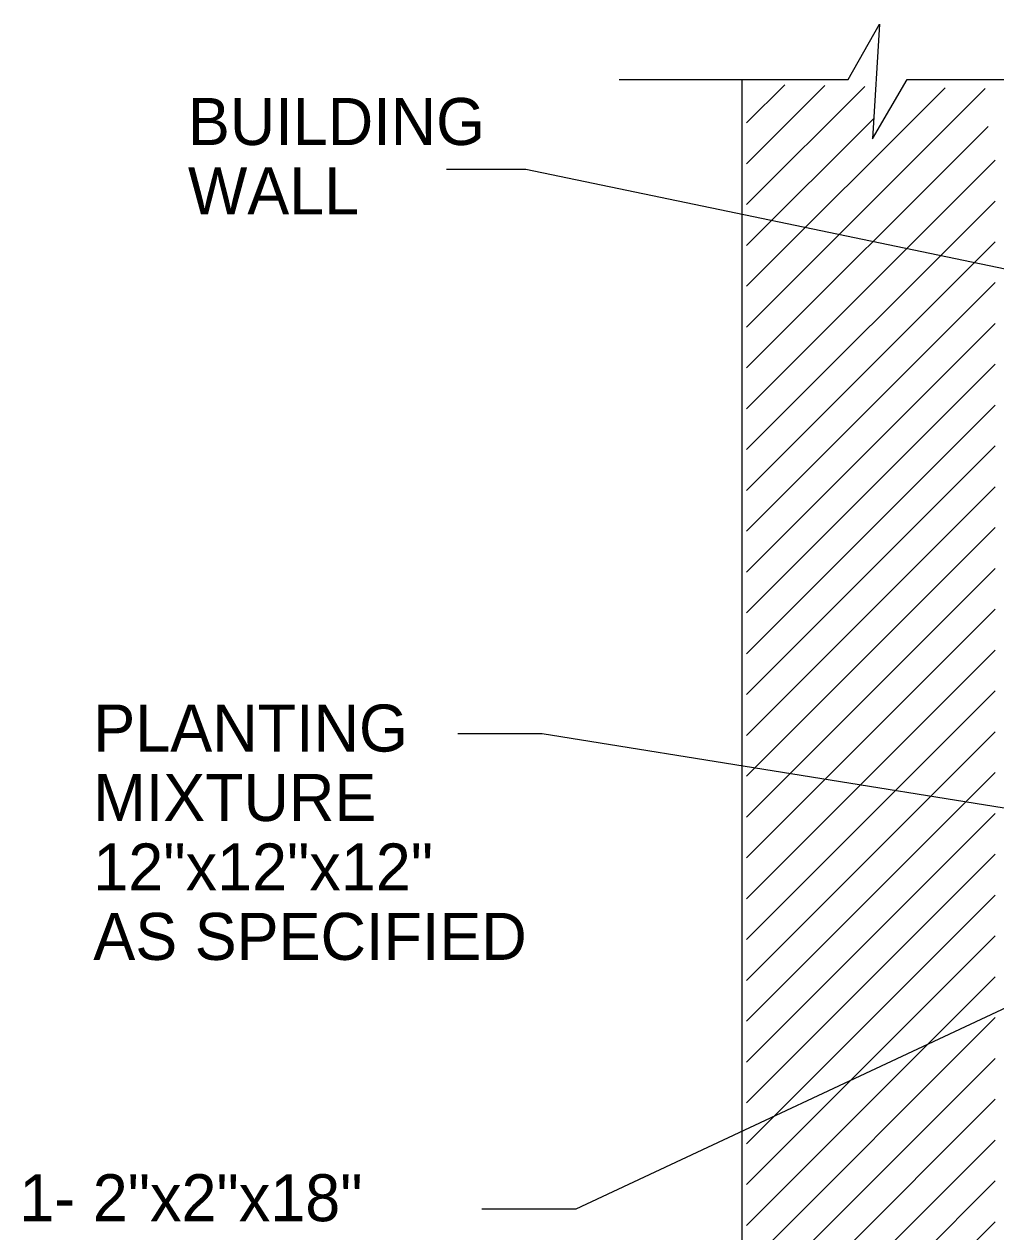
# Model space of a CAD drawing. Extents: x 10082 to 10257, y 10014 to 10069.
# Drawn here: x 10115.77 to 10130.23, y 10027 to 10044.97 of the extents above; entities that cross this region are included whole.
import ezdxf

# ---------------------------------------------------------------- set-up
doc = ezdxf.new("R2010")
doc.units = 0
for name, color, linetype in [('Default', 7, 'Continuous'), ('G-DETL-LINE', 7, 'Continuous'), ('G-DETL-PATT', 7, 'Continuous'), ('G-DETL-TEXT', 7, 'Continuous')]:
    doc.layers.add(name, color=color, linetype=linetype)

msp = doc.modelspace()

# ---------------------------------------------------------------- linework, layer by layer
at = {"layer": 'Default'}
for p, q in [((10123.231, 10042.808), (10122.053, 10042.808)), ((10132.364, 10040.908), (10123.231, 10042.808)), ((10123.475, 10034.406), (10122.219, 10034.406)), ((10134.29, 10032.667), (10123.475, 10034.406)), ((10136.446, 10033.178), (10123.976, 10027.333)), ((10123.976, 10027.333), (10122.578, 10027.333))]:
    msp.add_line(p, q, dxfattribs=at)
at = {"layer": 'G-DETL-LINE'}
for p, q in [((10128.03, 10044.143), (10128.493, 10044.969)), ((10128.493, 10044.969), (10128.39, 10043.262)), ((10124.618, 10044.143), (10128.03, 10044.143)), ((10128.39, 10043.262), (10128.904, 10044.143)), ((10128.904, 10044.143), (10132.704, 10044.143))]:
    msp.add_line(p, q, dxfattribs=at)
msp.add_lwpolyline([(10126.447, 10044.143), (10126.447, 10021.81)], dxfattribs=at)
at = {"layer": 'G-DETL-PATT'}
for p, q in [((10126.517, 10043.498), (10127.085, 10044.065)), ((10126.517, 10042.89), (10127.681, 10044.054)), ((10126.517, 10042.283), (10128.277, 10044.043)), ((10126.517, 10041.068), (10129.47, 10044.02)), ((10126.517, 10040.46), (10130.066, 10044.009)), ((10126.517, 10041.675), (10128.408, 10043.566)), ((10126.517, 10039.853), (10130.112, 10043.447)), ((10126.517, 10039.245), (10130.217, 10042.945)), ((10126.517, 10038.637), (10130.217, 10042.337)), ((10126.517, 10038.03), (10130.217, 10041.73)), ((10126.517, 10037.422), (10130.217, 10041.122)), ((10126.517, 10036.815), (10130.217, 10040.515)), ((10126.517, 10036.207), (10130.217, 10039.907)), ((10126.517, 10035.6), (10130.217, 10039.3)), ((10126.517, 10034.992), (10130.217, 10038.692)), ((10126.517, 10034.385), (10130.217, 10038.084)), ((10126.517, 10033.777), (10130.217, 10037.477)), ((10126.517, 10033.17), (10130.217, 10036.869)), ((10126.517, 10032.562), (10130.217, 10036.262)), ((10126.517, 10031.954), (10130.217, 10035.654)), ((10126.517, 10031.347), (10130.217, 10035.047)), ((10126.517, 10030.739), (10130.217, 10034.439)), ((10126.517, 10030.132), (10130.217, 10033.832)), ((10126.517, 10029.524), (10130.217, 10033.224)), ((10126.517, 10028.917), (10130.217, 10032.616)), ((10126.517, 10028.309), (10130.217, 10032.009)), ((10126.517, 10027.702), (10130.217, 10031.401)), ((10126.517, 10027.094), (10130.217, 10030.794)), ((10126.517, 10026.487), (10130.217, 10030.186)), ((10126.517, 10025.879), (10130.217, 10029.579)), ((10126.517, 10025.271), (10130.217, 10028.971)), ((10126.517, 10024.664), (10130.217, 10028.364)), ((10126.517, 10024.056), (10130.217, 10027.756)), ((10126.517, 10023.449), (10130.217, 10027.149))]:
    msp.add_line(p, q, dxfattribs=at)

# ---------------------------------------------------------------- texts
at = {"layer": 'G-DETL-TEXT'}
for s, p in [('BUILDING ', (10118.203, 10043.17)), ('WALL', (10118.203, 10042.137)), ('PLANTING ', (10116.795, 10034.144)), ('MIXTURE ', (10116.795, 10033.111)), ('12"x12"x12" ', (10116.795, 10032.077)), ('AS SPECIFIED', (10116.795, 10031.044)), ('1- 2"x2"x18" ', (10115.694, 10027.155))]:
    msp.add_text(s, height=0.7, dxfattribs=at).set_placement(p)

doc.saveas('drawing.dxf')
